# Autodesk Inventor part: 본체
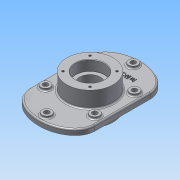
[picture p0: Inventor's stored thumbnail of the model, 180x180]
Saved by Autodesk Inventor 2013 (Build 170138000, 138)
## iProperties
Created: 2015-02
Part Number: 본체
Material: 알루미늄 6061
Document SubType Name: Modeling
Designer: Administrator
Density: 2.71 g/cm^3
Mass: 1662.1 g
Surface Area: 942.609 cm^2
Volume: 613.321 cm^3
Author: Administrator
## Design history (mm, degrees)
sketch "스케치1" dims "d41" = 50, "d42" = 50
  geometry: L1 (-70, -60)-(70, -60); L2 (70, -60)-(70, 60); L3 (70, 60)-(-70, 60); L4 (-70, 60)-(-70, -60); L5 (-70, -60)-(70, 60); L6 (70, -60)-(-70, 60); 3 further points; 2 other entities
  constraints: 12 end point, 4 midpoint, 3 horizontal, 2 parallel, 1 perpendicular, 8 other
  dimensions: "d0" = 140 distance of L2.end L3.end; "d1" = 120 distance of L2.end L1.end
extrude "돌출1" new body sketch "스케치1" distance "d3" = 12; taper "d4" = 0 deg
node "작업 평면1"
sketch "스케치2"
  geometry: C1 r 50 at (0, 0); 1 further point
  constraints: 1 centre point, 1 coincident
  dimensions: "d6" = 100 diameter of C1
extrude "돌출2" join sketch "스케치2" distance "d7" = 70; taper "d8" = 0 deg
sketch "스케치3"
  geometry: C1 r 50 at (0, 0) reference; C2 r 31 at (0, 0)
  constraints: 1 centre point, 1 coincident
  dimensions: "d9" = 62 diameter of C2
extrude "돌출3" cut sketch "스케치3" distance "d10" = 22; taper "d11" = 0 deg
hole "구멍1" diameter "d14" = 45; stored, may be unused: countersink angle "d18" = 90 deg, drill point angle "d20" = 118 deg; dims "d12" = 10, "d13" = 10, "d15" = 6, "d16" = 62, "d17" = 22, "d19" = 70
fillet "모깎기1" dims "d21" = 3
sketch "스케치4"
  geometry: L1 (0, 0)-(17.779, 0); C1 r 31 at (0, 0) reference; C2 r 50 at (0, 0) reference; 1 further point
  constraints: 2 end point, 1 horizontal
  dimensions: "d22" = 45 deg dimension on C1.centre point (-28.991, 28.991) L1.end; "d23" = 41 distance of point (-28.991, 28.991) C1.centre
hole "구멍2" sketch "스케치4" at (-28.991, 28.991) diameter "d24" = 4.917; stored, may be unused: countersink angle "d28" = 90 deg, drill point angle "d30" = 118 deg; dims "d25" = 10, "d26" = 62, "d27" = 22, "d29" = 13
node "작업 평면2"
fillet "모깎기2" dims "d34" = 0.3
chamfer "모따기1" distance "d35" = 1; stored, may be unused: second distance "d36" = 2, angle "d37" = 45 deg
sketch "스케치5"
  geometry: C1 r 50 at (0, 0) reference; 1 further point
  constraints: 1 vertical alignment, 1 other
  dimensions: "d38" = 65 distance of point (0, 65) C1.centre
feature "엠보싱1" sketch "스케치5" dims "d0" = 140, "d1" = 120, "d20" = 118 deg, "d39" = 1, "d40" = 0, "d41" = 50, "d42" = 50
sketch "스케치6"
  geometry: L1 (-67, -60)-(-67, 60) reference; L2 (67, 60)-(67, -60) reference; L3 (53, 60)-(53, -60); L4 (-53, -60)-(-53, 60); L5 (70, -60)-(70, 60) reference; C1 r 50 at (0, 0) reference; C2 r 10 at (0, 93); C3 r 10 at (-53, 42.733); C4 r 10 at (-53, -42.733); C5 r 10 at (0, -93); C6 r 10 at (53, 42.733); C7 r 10 at (53, -42.733)
  constraints: 6 centre point, 4 end point, 4 point on line, 3 parallel, 2 horizontal alignment, 2 vertical alignment, 8 other
  dimensions: "d43" = 17 distance between parallel lines of L3 L5; "d44" = 20 diameter of C2; "d46" = 20 diameter of C3; "d47" = 20 diameter of C4; "d49" = 85.46667 distance of C4.centre C3.centre; "d50" = 42.73333 vertical distance of C1.centre C3.centre; "d51" = 20 diameter of C5; "d52" = 20 diameter of C6; "d53" = 20 diameter of C7; "d54" = 85.46667 distance of C7.centre C6.centre; "d55" = 42.73333 vertical distance of C6.centre C1.centre
extrude "돌출4" join sketch "스케치6" distance "d56" = 5; taper "d57" = 0 deg
fillet "모깎기3" dims "d58" = 3
fillet "모깎기4" dims "d59" = 3
sketch "스케치7"
  geometry: C1 r 10 at (0, 0) reference; C2 r 10 at (-53, -50.267) reference; C3 r 10 at (-53, -135.733) reference; C4 r 10 at (0, -186) reference; C5 r 10 at (53, -135.733) reference; C6 r 10 at (53, -50.267) reference; 7 further points
  constraints: 6 coincident
hole "구멍3" sketch "스케치7" at (0, 0), (53, -50.267), (-53, -50.267), (-53, -135.733), (0, -186), (53, -135.733) diameter "d60" = 11; stored, may be unused: countersink angle "d64" = 90 deg, drill point angle "d66" = 118 deg; dims "d61" = 10, "d62" = 62, "d63" = 22, "d65" = 20
node "솔리드1"
pattern_circular "원형 패턴1" dims angle "d32" = 360 deg
mirror "대칭1"
node "투영된 루프1"
node "투영된 루프2"
node "투영된 루프3"
node "투영된 루프4"
node "투영된 루프5"
other parameters: "d5" = 23
